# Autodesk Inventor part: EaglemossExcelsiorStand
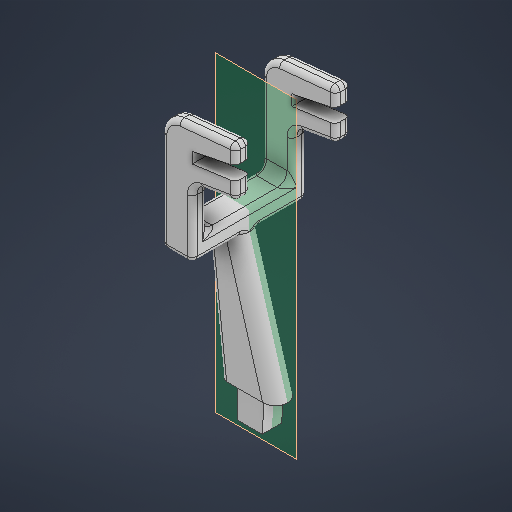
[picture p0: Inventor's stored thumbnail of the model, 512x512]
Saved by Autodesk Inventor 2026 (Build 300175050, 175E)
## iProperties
Created: 2025-11
Part Number: EaglemossExcelsiorStand
Material: Generic
Document SubType Name: Modeling
Designer: Andrew
Density: 1 g/cm^3
Appearance: Default
Author: Andrew
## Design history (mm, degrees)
sketch "Sketch1"
  geometry: L1 (2.5, 2)-(-2.5, 2); L2 (-2.5, 2)-(-2.5, -2); L3 (-2.5, -2)-(2.5, -2); L4 (2.5, -2)-(2.5, 2); 2 further points
  constraints: 8 end point, 2 parallel, 1 horizontal, 1 midpoint, 1 perpendicular
  dimensions: "d0" = 4 distance between parallel lines of L3 L1; "d1" = 2 distance from line of point (0, 0) L1 (= 0.5 x d0); "d2" = 5 distance from line of L2 point (2.5, 0); "d3" = 2.5 distance of point (0, 0) point (2.5, 0) (= 0.5 x d2)
extrude "Extrusion1" new body sketch "Sketch1" distance "d4" = 6.2; taper "d5" = 0 deg
sketch "Sketch2"
  geometry: L1 (5, 0)-(5, 6.2) reference; L2 (5, 6.2)-(5.4, 6.2); L3 (5.4, 6.2)-(5, 0); L4 (5, 0)-(5, 6.2); 1 further point
  constraints: 6 end point, 1 collinear, 1 horizontal
  dimensions: "d6" = 0.4 distance of L1.end L2.end
extrude "Extrusion2" join sketch "Sketch2" stored distance "d7" = 6.2; taper "d8" = 0 deg
sketch "Sketch4"
  geometry: L1 (-5.3, 6.2)-(-8.3, 32.7); L2 (-8.3, 32.7)-(-2.1, 32.7); L3 (-2.1, 32.7)-(5.7, 6.2); L4 (5.7, 6.2)-(-5.3, 6.2); L5 (2.9, 6.2)-(-2.5, 6.2) reference; 2 further points
  constraints: 8 end point, 1 horizontal, 1 midpoint, 1 parallel
  dimensions: "d14" = 11 distance of L1.start L3.end; "d15" = 5.5 distance of point (0.2, 6.2) L3.end (= 0.5 x d14); "d16" = 0 distance between parallel lines of L5 L4; "d17" = 26.5 distance between parallel lines of L4 L2; "d18" = 6.2 distance of L1.end L2.end; "d19" = 3 horizontal distance of L1.start L1.end
extrude "Extrusion3" join sketch "Sketch4" stored distance "d20" = 5; taper "d21" = 0 deg
fillet "Fillet1" dims "d22" = 2.5
sketch "Sketch6"
  geometry: L1 (0, 14.25)-(6.2, 14.25); L2 (6.2, 14.25)-(6.2, -9.25); L3 (6.2, -9.25)-(0, -9.25); L4 (0, -9.25)-(0, 14.25); L5 (0, 5)-(0, 0) reference; 4 further points; 1 other entity
  constraints: 8 end point, 2 midpoint, 2 parallel, 1 horizontal, 1 perpendicular, 1 vertical, 1 other
  dimensions: "d23" = 23.5 distance between parallel lines of L3 L1; "d24" = 11.75 distance from line of point (3.594, 2.5) L1 (= 0.5 x d23)
extrude "Extrusion4" join sketch "Sketch6" distance "d25" = 4; taper "d26" = 0 deg
sketch "Sketch7"
  geometry: L1 (0, 14.25)-(0, -9.25) reference; L2 (0, 14.25)-(6.2, 14.25); L3 (6.2, 14.25)-(6.2, 11.2); L4 (6.2, 11.2)-(0, 11.2); L5 (0, 11.2)-(0, 14.25); L6 (6.2, -9.25)-(6.2, 14.25) reference; L7 (6.2, -9.25)-(0, -9.25); L8 (0, -9.25)-(0, -6.2); L9 (0, -6.2)-(6.2, -6.2); L10 (6.2, -6.2)-(6.2, -9.25); 5 further points
  constraints: 16 end point, 4 parallel, 2 horizontal, 2 perpendicular, 2 point on line
  dimensions: "d28" = 17.4 distance between parallel lines of L9 L4; "d29" = 8.7 distance from line of point (8.3, 2.5) L4 (= 0.5 x d28)
extrude "Extrusion5" join sketch "Sketch7" distance "d30" = 20; taper "d31" = 0 deg
sketch "Sketch9"
  geometry: L1 (6.2, 4)-(6.2, 24) reference; L2 (6.2, 24)-(15.074, 25.5); L3 (15.074, 25.5)-(15.074, 21.95); L4 (15.074, 21.95)-(6.2, 20.45); L5 (6.2, 20.45)-(6.2, 24); L6 (6.2, 14.061)-(15.074, 15.561); L7 (15.074, 15.561)-(15.074, 19.111); L8 (15.074, 19.111)-(6.2, 17.611); L9 (6.2, 17.611)-(6.2, 14.061); L10 (6.2, 0)-(6.2, 24) reference; 7 further points
  constraints: 16 end point, 5 parallel, 4 midpoint, 2 collinear, 2 point on line
  dimensions: "d33" = 9 distance of point (6.2, 22.225) point (15.074, 23.725); "d34" = 3.5 distance between parallel lines of L4 L2; "d35" = 3.5 distance between parallel lines of L6 L8; "d49" = 2.8 distance between parallel lines of L4 L8; "d50" = 1.5 vertical distance of L6.start L6.end
extrude "Extrusion6" join sketch "Sketch9" stored distance "d36" = 20; taper "d37" = 0 deg
fillet "Fillet2" dims "d38" = 2.5
chamfer "Chamfer3" distance "d51" = 0.3; stored, may be unused: second distance "d52" = 9, angle "d53" = 89 deg
chamfer "Chamfer4" distance "d54" = 0.3; stored, may be unused: second distance "d55" = 9, angle "d56" = 89 deg
sketch "Sketch10"
  geometry: L1 (0, 24)-(6.2, 24) reference; L2 (15.074, 25.5)-(6.2, 24) reference; L3 (0, 4)-(0, 24) reference; L4 (0, 24)-(15.074, 25.5); 2 further points
  constraints: 2 end point
extrude "Extrusion7" join sketch "Sketch10" stored distance "d57" = 10; taper "d58" = 0 deg
mirror "Mirror1"
fillet "Fillet3" dims "d45" = 4
fillet "Fillet4" dims "d46" = 1
fillet "Fillet5" dims "d47" = 1
fillet "Fillet6" dims "d59" = 2
body "Solid1"
workplane "Work Plane1"
